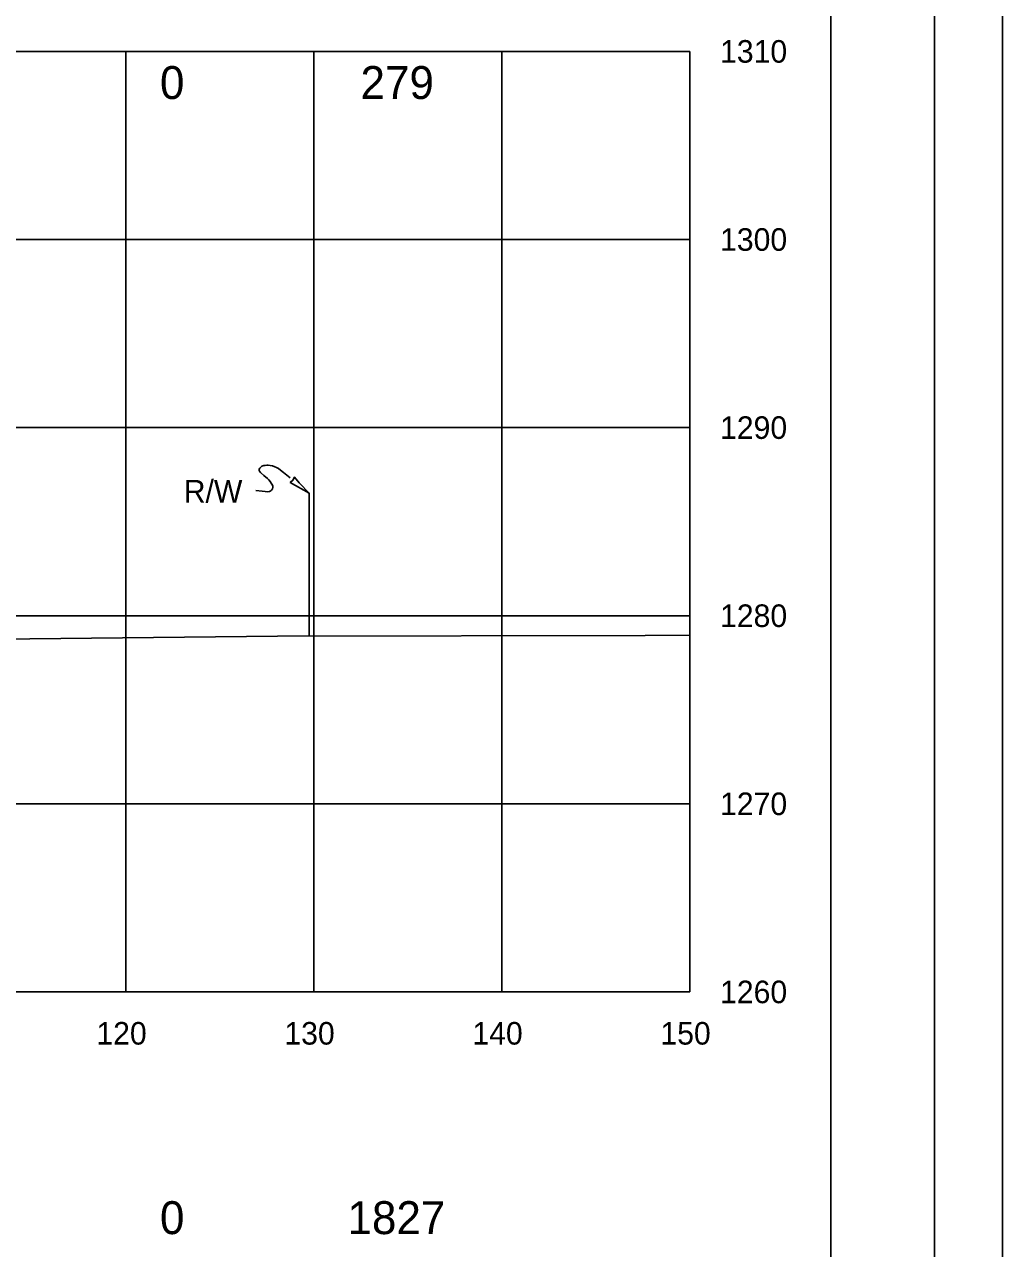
# Model space of a CAD drawing. Extents: x 2148105 to 2149976, y 144169 to 149705.
# Drawn here: x 2148527.9 to 2148579.9, y 145523.3 to 145588.3 of the extents above; entities that cross this region are included whole.
import ezdxf

# ---------------------------------------------------------------- set-up
doc = ezdxf.new("R2010")
doc.units = 0
for name, color, linetype in [('PH1a-PR-ServRd', 7, 'Continuous'), ('PR_Align_Ramp_A', 7, 'Continuous'), ('PR_Align_Ramp_E', 7, 'Continuous'), ('PR_Align_Ramp_J', 7, 'Continuous'), ('PR_Storm_Conc_Box_PH1B', 7, 'Continuous'), ('PR_Storm_Conc_Pipe_PH1B', 7, 'Continuous'), ('PR_Storm_Inlet_CICI_PH1B', 7, 'Continuous'), ('PR_Storm_MH_PH1B', 7, 'Continuous'), ('PR_Storm_Standard_Median_Drain_PH1B', 7, 'Continuous'), ('TOPO_BRIDGE_Low Beam', 7, 'Continuous')]:
    doc.layers.add(name, color=color, linetype=linetype)

msp = doc.modelspace()

# ---------------------------------------------------------------- linework, layer by layer
at = {"layer": 'PH1a-PR-ServRd'}
msp.add_lwpolyline([(2148570.822, 145401.906), (2148255.822, 145401.906), (2148255.822, 145611.906), (2148570.822, 145611.906)], close=True, dxfattribs=at)
at = {"layer": 'PR_Align_Ramp_E'}
msp.add_lwpolyline([(2148219.947, 145625.156), (2148579.947, 145625.156), (2148579.947, 145385.156), (2148219.947, 145385.156)], close=True, dxfattribs=at)
at = {"layer": 'PR_Align_Ramp_J'}
msp.add_lwpolyline([(2148236.322, 145616.906), (2148576.322, 145616.906), (2148576.322, 145396.906), (2148236.322, 145396.906)], close=True, dxfattribs=at)
at = {"layer": 'PR_Storm_Conc_Box_PH1B'}
for p, q in [((2148263.322, 145586.906), (2148563.322, 145586.906)), ((2148533.322, 145536.906), (2148533.322, 145586.906)), ((2148543.322, 145536.906), (2148543.322, 145586.906)), ((2148553.322, 145536.906), (2148553.322, 145586.906)), ((2148563.322, 145536.906), (2148563.322, 145586.906)), ((2148263.322, 145576.906), (2148563.322, 145576.906)), ((2148263.322, 145566.906), (2148563.322, 145566.906)), ((2148263.322, 145556.906), (2148563.322, 145556.906)), ((2148263.322, 145546.906), (2148563.322, 145546.906)), ((2148263.322, 145536.906), (2148563.322, 145536.906))]:
    msp.add_line(p, q, dxfattribs=at)
at = {"layer": 'PR_Storm_Conc_Pipe_PH1B'}
msp.add_lwpolyline([(2148255.822, 145401.906), (2148570.822, 145401.906), (2148570.822, 145611.906), (2148255.822, 145611.906)], close=True, dxfattribs=at)
msp.add_lwpolyline([(2148255.822, 145401.906), (2148570.822, 145401.906), (2148570.822, 145611.906), (2148255.822, 145611.906)], close=True, dxfattribs=at)
at = {"layer": 'PR_Storm_Inlet_CICI_PH1B'}
msp.add_lwpolyline([(2148360.144, 145558.297), (2148370.113, 145558.283), (2148387.186, 145558.18), (2148408.984, 145557.543), (2148414.914, 145557.383), (2148436.575, 145556.802), (2148440.723, 145556.683), (2148481.736, 145556.143), (2148482.15, 145556.15), (2148482.508, 145556.152), (2148492.834, 145556.238), (2148495.998, 145556.097), (2148498.628, 145556.083), (2148499.794, 145556.017), (2148509.998, 145555.925), (2148515.751, 145555.7), (2148518.446, 145555.599), (2148519.956, 145555.587), (2148541.378, 145555.816), (2148560.942, 145555.859), (2148563.322, 145555.869)], dxfattribs=at)
at = {"layer": 'PR_Storm_Standard_Median_Drain_PH1B'}
for p, q in [((2148563.322, 145536.906), (2148563.322, 145586.906)), ((2148263.322, 145536.906), (2148563.322, 145536.906))]:
    msp.add_line(p, q, dxfattribs=at)
at = {"layer": 'TOPO_BRIDGE_Low Beam'}
msp.add_line((2148543.059, 145555.82), (2148543.059, 145563.42), dxfattribs=at)
for points in [[(2148542.048, 145564.231), (2148541.696, 145564.523), (2148541.534, 145564.651), (2148541.437, 145564.726), (2148541.337, 145564.781), (2148541.24, 145564.828), (2148541.123, 145564.866), (2148540.988, 145564.896), (2148540.895, 145564.905), (2148540.812, 145564.905), (2148540.728, 145564.898), (2148540.657, 145564.884), (2148540.605, 145564.87), (2148540.551, 145564.849), (2148540.508, 145564.822), (2148540.471, 145564.791), (2148540.435, 145564.748), (2148540.405, 145564.691), (2148540.408, 145564.633), (2148540.419, 145564.594), (2148540.473, 145564.525), (2148540.662, 145564.363), (2148540.847, 145564.199), (2148540.925, 145564.124), (2148540.988, 145564.049), (2148541.051, 145563.955), (2148541.088, 145563.893), (2148541.128, 145563.804), (2148541.134, 145563.727), (2148541.112, 145563.643), (2148541.07, 145563.574), (2148541.021, 145563.539), (2148540.964, 145563.516), (2148540.853, 145563.499), (2148540.72, 145563.507), (2148540.563, 145563.523), (2148540.228, 145563.559)], [(2148543.059, 145563.42), (2148542.543, 145563.97), (2148542.282, 145564.277), (2148542.2, 145564.109), (2148542.057, 145563.995), (2148543.059, 145563.42)]]:
    msp.add_lwpolyline(points, dxfattribs=at)

# ---------------------------------------------------------------- texts
at = {"layer": 'PR_Align_Ramp_A'}
for s, p in [('0', (2148535.131, 145584.375)), ('279', (2148545.798, 145584.375)), ('0', (2148535.131, 145524.031)), ('1827', (2148545.106, 145524.031))]:
    msp.add_text(s, height=1.75, dxfattribs=at).set_placement(p)
at = {"layer": 'PR_Storm_MH_PH1B'}
for s, p in [('1310', (2148564.922, 145586.306)), ('1300', (2148564.922, 145576.306)), ('1290', (2148564.922, 145566.306)), ('1280', (2148564.922, 145556.306)), ('1270', (2148564.922, 145546.306)), ('1260', (2148564.922, 145536.306)), ('120', (2148531.749, 145534.106)), ('130', (2148541.749, 145534.106)), ('140', (2148551.749, 145534.106)), ('150', (2148561.749, 145534.106))]:
    msp.add_text(s, height=1.2, dxfattribs=at).set_placement(p)
at = {"layer": 'TOPO_BRIDGE_Low Beam'}
msp.add_text('R/W', height=1.2, rotation=360, dxfattribs=at).set_placement((2148536.396, 145562.923))

doc.saveas('drawing.dxf')
